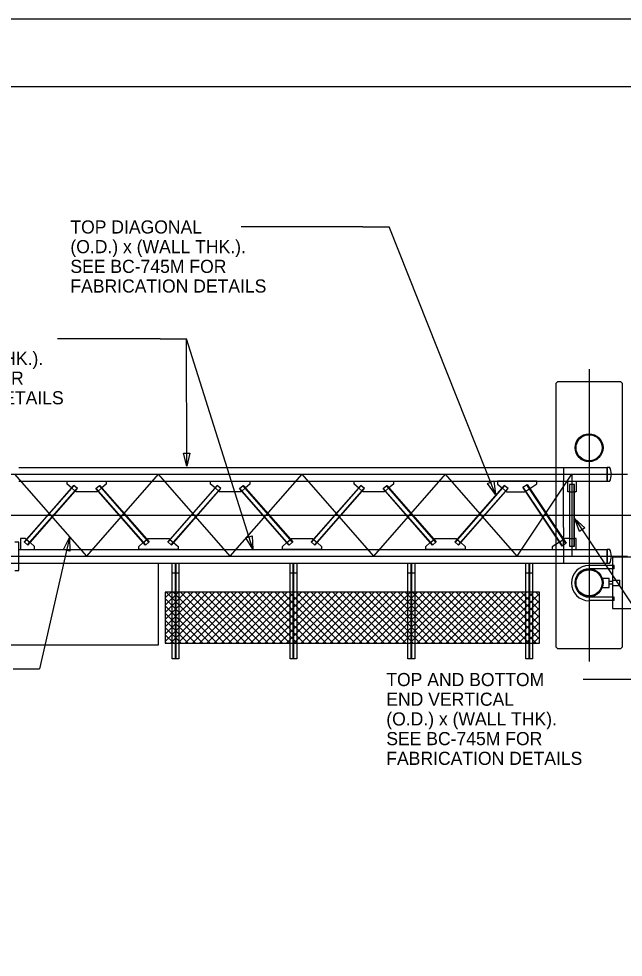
# Model space of a CAD drawing. Extents: x 3831399 to 3833095, y 499014 to 500202.
# Drawn here: x 3832620 to 3832754.1, y 499994 to 500202 of the extents above; entities that cross this region are included whole.
import ezdxf

# ---------------------------------------------------------------- set-up
doc = ezdxf.new("R2010")
doc.units = 0
for name, color, linetype in [('0-catwalk', 7, 'Continuous'), ('0-DEVICE ATTACH', 7, 'Continuous'), ('0-foundation', 7, 'Continuous'), ('0-sign', 7, 'Continuous'), ('0-truss', 7, 'Continuous'), ('2', 7, 'Continuous'), ('CenterLine', 7, 'Continuous'), ('DIM TXT', 7, 'Continuous'), ('PLT-BNDY', 7, 'Continuous'), ('structure', 7, 'Continuous')]:
    doc.layers.add(name, color=color, linetype=linetype)

msp = doc.modelspace()

# ---------------------------------------------------------------- linework, layer by layer
at = {"layer": '0-catwalk'}
for p, q in [((3832654.05, 500060.19), (3832654.05, 500081.38)), ((3832654.05, 500081.38), (3832655.54, 500081.38)), ((3832654.77, 500060.19), (3832654.77, 500081.38)), ((3832654.77, 500081.38), (3832654.83, 500081.38)), ((3832654.83, 500081.38), (3832654.83, 500060.19)), ((3832655.54, 500081.38), (3832655.54, 500060.19)), ((3832680.19, 500060.19), (3832680.19, 500081.38)), ((3832680.19, 500081.38), (3832681.69, 500081.38)), ((3832680.91, 500060.19), (3832680.91, 500081.38)), ((3832680.91, 500081.38), (3832680.97, 500081.38)), ((3832680.97, 500081.38), (3832680.97, 500060.19)), ((3832681.69, 500081.38), (3832681.69, 500060.19)), ((3832706.34, 500060.19), (3832706.34, 500081.38)), ((3832706.34, 500081.38), (3832707.83, 500081.38)), ((3832707.05, 500060.19), (3832707.05, 500081.38)), ((3832707.05, 500081.38), (3832707.12, 500081.38)), ((3832707.12, 500081.38), (3832707.12, 500060.19)), ((3832707.83, 500081.38), (3832707.83, 500060.19)), ((3832732.48, 500060.19), (3832732.48, 500081.38)), ((3832732.48, 500081.38), (3832733.98, 500081.38)), ((3832733.2, 500060.19), (3832733.2, 500081.38)), ((3832733.2, 500081.38), (3832733.26, 500081.38)), ((3832733.26, 500081.38), (3832733.26, 500060.19)), ((3832733.98, 500081.38), (3832733.98, 500060.19)), ((3832735.5, 500074.96), (3832652.52, 500074.96)), ((3832652.52, 500074.96), (3832652.52, 500063.6)), ((3832652.52, 500064.02), (3832663.47, 500074.96)), ((3832652.52, 500065.63), (3832661.86, 500074.96)), ((3832652.52, 500067.23), (3832660.25, 500074.96)), ((3832652.52, 500068.84), (3832658.65, 500074.96)), ((3832652.52, 500070.45), (3832657.04, 500074.96)), ((3832652.52, 500072.06), (3832655.43, 500074.96)), ((3832652.52, 500073.66), (3832653.82, 500074.96)), ((3832652.52, 500073.52), (3832662.45, 500063.6)), ((3832652.69, 500074.96), (3832664.06, 500063.6)), ((3832653.71, 500063.6), (3832665.08, 500074.96)), ((3832654.3, 500074.96), (3832665.67, 500063.6)), ((3832655.32, 500063.6), (3832666.68, 500074.96)), ((3832655.91, 500074.96), (3832667.27, 500063.6)), ((3832656.92, 500063.6), (3832668.29, 500074.96)), ((3832657.51, 500074.96), (3832668.88, 500063.6)), ((3832658.53, 500063.6), (3832669.9, 500074.96)), ((3832659.12, 500074.96), (3832670.49, 500063.6)), ((3832660.14, 500063.6), (3832671.51, 500074.96)), ((3832660.73, 500074.96), (3832672.1, 500063.6)), ((3832661.75, 500063.6), (3832673.11, 500074.96)), ((3832662.34, 500074.96), (3832673.7, 500063.6)), ((3832663.35, 500063.6), (3832674.72, 500074.96)), ((3832663.94, 500074.96), (3832675.31, 500063.6)), ((3832664.96, 500063.6), (3832676.33, 500074.96)), ((3832665.55, 500074.96), (3832676.92, 500063.6)), ((3832666.57, 500063.6), (3832677.94, 500074.96)), ((3832667.16, 500074.96), (3832678.53, 500063.6)), ((3832668.18, 500063.6), (3832679.54, 500074.96)), ((3832668.77, 500074.96), (3832680.13, 500063.6)), ((3832669.78, 500063.6), (3832681.15, 500074.96)), ((3832670.37, 500074.96), (3832681.74, 500063.6)), ((3832671.39, 500063.6), (3832682.76, 500074.96)), ((3832671.98, 500074.96), (3832683.35, 500063.6)), ((3832673, 500063.6), (3832684.37, 500074.96)), ((3832673.59, 500074.96), (3832684.96, 500063.6)), ((3832674.61, 500063.6), (3832685.97, 500074.96)), ((3832675.2, 500074.96), (3832686.56, 500063.6)), ((3832676.21, 500063.6), (3832687.58, 500074.96)), ((3832676.8, 500074.96), (3832688.17, 500063.6)), ((3832677.82, 500063.6), (3832689.19, 500074.96)), ((3832678.41, 500074.96), (3832689.78, 500063.6)), ((3832679.43, 500063.6), (3832690.8, 500074.96)), ((3832680.02, 500074.96), (3832691.39, 500063.6)), ((3832681.04, 500063.6), (3832692.4, 500074.96)), ((3832681.63, 500074.96), (3832692.99, 500063.6)), ((3832682.64, 500063.6), (3832694.01, 500074.96)), ((3832683.23, 500074.96), (3832694.6, 500063.6)), ((3832684.25, 500063.6), (3832695.62, 500074.96)), ((3832684.84, 500074.96), (3832696.21, 500063.6)), ((3832685.86, 500063.6), (3832697.23, 500074.96)), ((3832686.45, 500074.96), (3832697.82, 500063.6)), ((3832687.47, 500063.6), (3832698.83, 500074.96)), ((3832688.06, 500074.96), (3832699.42, 500063.6)), ((3832689.07, 500063.6), (3832700.44, 500074.96)), ((3832689.66, 500074.96), (3832701.03, 500063.6)), ((3832690.68, 500063.6), (3832702.05, 500074.96)), ((3832691.27, 500074.96), (3832702.64, 500063.6)), ((3832692.29, 500063.6), (3832703.66, 500074.96)), ((3832692.88, 500074.96), (3832704.25, 500063.6)), ((3832693.9, 500063.6), (3832705.26, 500074.96)), ((3832694.49, 500074.96), (3832705.85, 500063.6)), ((3832695.5, 500063.6), (3832706.87, 500074.96)), ((3832696.09, 500074.96), (3832707.46, 500063.6)), ((3832697.11, 500063.6), (3832708.48, 500074.96)), ((3832697.7, 500074.96), (3832709.07, 500063.6)), ((3832698.72, 500063.6), (3832710.09, 500074.96)), ((3832699.31, 500074.96), (3832710.68, 500063.6)), ((3832700.33, 500063.6), (3832711.69, 500074.96)), ((3832700.92, 500074.96), (3832712.28, 500063.6)), ((3832701.93, 500063.6), (3832713.3, 500074.96)), ((3832702.53, 500074.96), (3832713.89, 500063.6)), ((3832703.54, 500063.6), (3832714.91, 500074.96)), ((3832704.13, 500074.96), (3832715.5, 500063.6)), ((3832705.15, 500063.6), (3832716.52, 500074.96)), ((3832705.74, 500074.96), (3832717.11, 500063.6)), ((3832706.76, 500063.6), (3832718.12, 500074.96)), ((3832707.35, 500074.96), (3832718.71, 500063.6)), ((3832708.36, 500063.6), (3832719.73, 500074.96)), ((3832708.96, 500074.96), (3832720.32, 500063.6)), ((3832709.97, 500063.6), (3832721.34, 500074.96)), ((3832710.56, 500074.96), (3832721.93, 500063.6)), ((3832711.58, 500063.6), (3832722.95, 500074.96)), ((3832712.17, 500074.96), (3832723.54, 500063.6)), ((3832713.19, 500063.6), (3832724.55, 500074.96)), ((3832713.78, 500074.96), (3832725.14, 500063.6)), ((3832714.79, 500063.6), (3832726.16, 500074.96)), ((3832715.39, 500074.96), (3832726.75, 500063.6)), ((3832716.4, 500063.6), (3832727.77, 500074.96)), ((3832716.99, 500074.96), (3832728.36, 500063.6)), ((3832718.01, 500063.6), (3832729.38, 500074.96)), ((3832718.6, 500074.96), (3832729.97, 500063.6)), ((3832719.62, 500063.6), (3832730.98, 500074.96)), ((3832720.21, 500074.96), (3832731.57, 500063.6)), ((3832721.22, 500063.6), (3832732.59, 500074.96)), ((3832721.82, 500074.96), (3832733.18, 500063.6)), ((3832722.83, 500063.6), (3832734.2, 500074.96)), ((3832723.42, 500074.96), (3832734.79, 500063.6)), ((3832724.44, 500063.6), (3832735.5, 500074.66)), ((3832725.03, 500074.96), (3832735.5, 500064.49)), ((3832726.64, 500074.96), (3832735.5, 500066.1)), ((3832728.25, 500074.96), (3832735.5, 500067.71)), ((3832729.85, 500074.96), (3832735.5, 500069.31)), ((3832731.46, 500074.96), (3832735.5, 500070.92)), ((3832733.07, 500074.96), (3832735.5, 500072.53)), ((3832734.68, 500074.96), (3832735.5, 500074.14)), ((3832735.5, 500063.6), (3832735.5, 500074.96)), ((3832652.52, 500071.92), (3832660.84, 500063.6)), ((3832726.05, 500063.6), (3832735.5, 500073.05)), ((3832727.66, 500063.6), (3832735.5, 500071.44)), ((3832652.52, 500070.31), (3832659.24, 500063.6)), ((3832729.26, 500063.6), (3832735.5, 500069.84)), ((3832652.52, 500068.7), (3832657.63, 500063.6)), ((3832730.87, 500063.6), (3832735.5, 500068.23)), ((3832652.52, 500067.09), (3832656.02, 500063.6)), ((3832652.52, 500065.49), (3832654.41, 500063.6)), ((3832732.48, 500063.6), (3832735.5, 500066.62)), ((3832652.52, 500063.88), (3832652.81, 500063.6)), ((3832652.52, 500063.6), (3832735.5, 500063.6)), ((3832734.09, 500063.6), (3832735.5, 500065.01)), ((3832655.54, 500060.19), (3832654.05, 500060.19)), ((3832654.83, 500060.19), (3832654.77, 500060.19)), ((3832681.69, 500060.19), (3832680.19, 500060.19)), ((3832680.97, 500060.19), (3832680.91, 500060.19)), ((3832707.83, 500060.19), (3832706.34, 500060.19)), ((3832707.12, 500060.19), (3832707.05, 500060.19)), ((3832733.98, 500060.19), (3832732.48, 500060.19)), ((3832733.26, 500060.19), (3832733.2, 500060.19))]:
    msp.add_line(p, q, dxfattribs=at)
for points in [[(3832654.63, 500081.28), (3832654.05, 500081.28), (3832654.05, 500081.37), (3832655.54, 500081.37), (3832655.54, 500081.28), (3832654.96, 500081.28)], [(3832654.77, 500079.34), (3832654.77, 500081.15)], [(3832654.83, 500081.15), (3832654.83, 500079.34)], [(3832680.78, 500081.28), (3832680.19, 500081.28), (3832680.19, 500081.37), (3832681.69, 500081.37), (3832681.69, 500081.28), (3832681.11, 500081.28)], [(3832680.91, 500079.34), (3832680.91, 500081.15)], [(3832680.97, 500081.15), (3832680.97, 500079.34)], [(3832706.92, 500081.28), (3832706.34, 500081.28), (3832706.34, 500081.37), (3832707.83, 500081.37), (3832707.83, 500081.28), (3832707.25, 500081.28)], [(3832707.05, 500079.34), (3832707.05, 500081.15)], [(3832707.12, 500081.15), (3832707.12, 500079.34)], [(3832733.07, 500081.28), (3832732.48, 500081.28), (3832732.48, 500081.37), (3832733.98, 500081.37), (3832733.98, 500081.28), (3832733.39, 500081.28)], [(3832733.2, 500079.34), (3832733.2, 500081.15)], [(3832733.26, 500081.15), (3832733.26, 500079.34)], [(3832655.54, 500079.13), (3832654.05, 500079.13), (3832654.05, 500079.21), (3832654.63, 500079.21)], [(3832654.96, 500079.21), (3832655.54, 500079.21), (3832655.54, 500079.13)], [(3832681.69, 500079.13), (3832680.19, 500079.13), (3832680.19, 500079.21), (3832680.78, 500079.21)], [(3832681.11, 500079.21), (3832681.69, 500079.21), (3832681.69, 500079.13)], [(3832707.83, 500079.13), (3832706.34, 500079.13), (3832706.34, 500079.21), (3832706.92, 500079.21)], [(3832707.25, 500079.21), (3832707.83, 500079.21), (3832707.83, 500079.13)], [(3832733.98, 500079.13), (3832732.48, 500079.13), (3832732.48, 500079.21), (3832733.07, 500079.21)], [(3832733.39, 500079.21), (3832733.98, 500079.21), (3832733.98, 500079.13)]]:
    msp.add_lwpolyline(points, dxfattribs=at)
for centre, start, end in [((3832654.63, 500081.15), 0, 90), ((3832654.96, 500081.15), 90, 180), ((3832680.78, 500081.15), 0, 90), ((3832681.11, 500081.15), 90, 180), ((3832706.92, 500081.15), 0, 90), ((3832707.25, 500081.15), 90, 180), ((3832733.07, 500081.15), 0, 90), ((3832733.39, 500081.15), 90, 180), ((3832654.63, 500079.34), 270, 0), ((3832654.96, 500079.34), 180, 270), ((3832680.78, 500079.34), 270, 0), ((3832681.11, 500079.34), 180, 270), ((3832706.92, 500079.34), 270, 0), ((3832707.25, 500079.34), 180, 270), ((3832733.07, 500079.34), 270, 0), ((3832733.39, 500079.34), 180, 270)]:
    msp.add_arc(centre, 0.132, start, end, dxfattribs=at)
at = {"layer": '0-DEVICE ATTACH'}
for p, q in [((3832757.96, 500082.68), (3832751.71, 500082.68)), ((3832751.71, 500082.68), (3832751.71, 500071.31)), ((3832751.78, 500077.58), (3832753.3, 500077.58)), ((3832751.78, 500076.44), (3832753.3, 500076.44)), ((3832751.71, 500071.31), (3832757.96, 500071.31))]:
    msp.add_line(p, q, dxfattribs=at)
at = {"layer": '0-foundation'}
for p, q in [((3832739.48, 500121.53), (3832739.1, 500121.15)), ((3832753.5, 500121.53), (3832739.48, 500121.53)), ((3832753.88, 500121.15), (3832753.5, 500121.53)), ((3832739.1, 500121.15), (3832739.1, 500062.8)), ((3832753.88, 500062.8), (3832753.88, 500121.15)), ((3832740.81, 500102.58), (3832740.81, 500099.55)), ((3832740.81, 500089.26), (3832740.81, 500099.55)), ((3832740.81, 500089.26), (3832740.81, 500087.3)), ((3832740.81, 500085.5), (3832740.81, 500087.3)), ((3832740.81, 500085.5), (3832740.81, 500081.37)), ((3832739.1, 500062.8), (3832739.48, 500062.42)), ((3832739.48, 500062.42), (3832753.5, 500062.42)), ((3832753.5, 500062.42), (3832753.88, 500062.8))]:
    msp.add_line(p, q, dxfattribs=at)
at = {"layer": '0-sign'}
for p, q in [((3832537.29, 500081.37), (3832650.95, 500081.37)), ((3832650.95, 500081.37), (3832650.95, 500063.18)), ((3832650.95, 500063.18), (3832537.29, 500063.18))]:
    msp.add_line(p, q, dxfattribs=at)
at = {"layer": '0-truss'}
for p, q in [((3832620.03, 500102.58), (3832750.49, 500102.58)), ((3832750.49, 500102.66), (3832751.05, 500102.66)), ((3832750.49, 500102.58), (3832750.49, 500099.55)), ((3832620.03, 500099.55), (3832750.49, 500099.55)), ((3832632.22, 500098.61), (3832621.24, 500086.06)), ((3832621.3, 500086.01), (3832632.28, 500098.56)), ((3832631.72, 500098.04), (3832630.74, 500098.9)), ((3832633.04, 500097.89), (3832632.22, 500098.61)), ((3832637.15, 500097.89), (3832637.97, 500098.61)), ((3832648.89, 500086.01), (3832637.91, 500098.56)), ((3832637.97, 500098.61), (3832648.95, 500086.06)), ((3832639.45, 500098.9), (3832638.47, 500098.04)), ((3832664.05, 500098.61), (3832653.07, 500086.06)), ((3832653.12, 500086.01), (3832664.1, 500098.56)), ((3832663.55, 500098.04), (3832662.56, 500098.9)), ((3832664.87, 500097.89), (3832664.05, 500098.61)), ((3832668.98, 500097.89), (3832669.8, 500098.61)), ((3832680.72, 500086.01), (3832669.74, 500098.56)), ((3832669.8, 500098.61), (3832680.78, 500086.06)), ((3832671.28, 500098.9), (3832670.29, 500098.04)), ((3832695.87, 500098.61), (3832684.89, 500086.06)), ((3832684.95, 500086.01), (3832695.93, 500098.56)), ((3832695.38, 500098.04), (3832694.39, 500098.9)), ((3832696.69, 500097.89), (3832695.87, 500098.61)), ((3832700.81, 500097.89), (3832701.63, 500098.61)), ((3832712.55, 500086.01), (3832701.57, 500098.56)), ((3832701.63, 500098.61), (3832712.61, 500086.06)), ((3832703.11, 500098.9), (3832702.12, 500098.04)), ((3832727.7, 500098.61), (3832716.72, 500086.06)), ((3832727.76, 500098.56), (3832716.78, 500086.01)), ((3832726.22, 500098.9), (3832727.2, 500098.04)), ((3832728.52, 500097.89), (3832727.7, 500098.61)), ((3832731.84, 500098.19), (3832732.75, 500098.8)), ((3832741.37, 500085.72), (3832732.68, 500098.75)), ((3832732.75, 500098.8), (3832741.44, 500085.76)), ((3832733.34, 500097.9), (3832734.93, 500098.96)), ((3832742.16, 500098.8), (3832742.16, 500085.15)), ((3832743.25, 500098.8), (3832742.16, 500098.8)), ((3832742.23, 500085.15), (3832742.23, 500098.8)), ((3832743.17, 500085.15), (3832743.17, 500098.8)), ((3832743.25, 500085.15), (3832743.25, 500098.8)), ((3832622, 500085.39), (3832632.98, 500097.94)), ((3832622.06, 500085.34), (3832633.04, 500097.89)), ((3832631.72, 500098.04), (3832632.54, 500097.32)), ((3832632.76, 500097.14), (3832632.54, 500097.32)), ((3832648.13, 500085.34), (3832637.15, 500097.89)), ((3832648.19, 500085.39), (3832637.21, 500097.94)), ((3832637.65, 500097.32), (3832637.43, 500097.14)), ((3832637.65, 500097.32), (3832638.47, 500098.04)), ((3832653.83, 500085.39), (3832664.81, 500097.94)), ((3832653.89, 500085.34), (3832664.87, 500097.89)), ((3832663.55, 500098.04), (3832664.37, 500097.32)), ((3832664.58, 500097.14), (3832664.37, 500097.32)), ((3832679.96, 500085.34), (3832668.98, 500097.89)), ((3832680.02, 500085.39), (3832669.04, 500097.94)), ((3832669.47, 500097.32), (3832669.26, 500097.14)), ((3832669.47, 500097.32), (3832670.29, 500098.04)), ((3832685.65, 500085.39), (3832696.63, 500097.94)), ((3832685.71, 500085.34), (3832696.69, 500097.89)), ((3832695.38, 500098.04), (3832696.2, 500097.32)), ((3832696.41, 500097.14), (3832696.2, 500097.32)), ((3832711.79, 500085.34), (3832700.81, 500097.89)), ((3832711.84, 500085.39), (3832700.86, 500097.94)), ((3832701.3, 500097.32), (3832701.09, 500097.14)), ((3832701.3, 500097.32), (3832702.12, 500098.04)), ((3832728.46, 500097.94), (3832717.48, 500085.39)), ((3832717.54, 500085.34), (3832728.52, 500097.89)), ((3832727.2, 500098.04), (3832728.02, 500097.32)), ((3832728.02, 500097.32), (3832728.24, 500097.14)), ((3832728.24, 500097.14), (3832732.2, 500097.14)), ((3832740.53, 500085.15), (3832731.84, 500098.19)), ((3832740.6, 500085.2), (3832731.9, 500098.23)), ((3832732.2, 500097.14), (3832732.44, 500097.3)), ((3832732.44, 500097.3), (3832733.34, 500097.9)), ((3832742.16, 500097.14), (3832743.25, 500097.14)), ((3832620.03, 500086.03), (3832619.18, 500086.03)), ((3832620.03, 500079.73), (3832620.03, 500086.03)), ((3832621.52, 500086.81), (3832620.41, 500086.81)), ((3832620.41, 500086.81), (3832620.41, 500086.81)), ((3832620.41, 500086.81), (3832620.41, 500084.4)), ((3832621.24, 500086.06), (3832622.06, 500085.34)), ((3832621.73, 500086.63), (3832621.52, 500086.81)), ((3832621.73, 500086.63), (3832622.55, 500085.91)), ((3832623.54, 500085.05), (3832622.55, 500085.91)), ((3832646.65, 500085.05), (3832647.64, 500085.91)), ((3832647.64, 500085.91), (3832648.46, 500086.63)), ((3832648.95, 500086.06), (3832648.13, 500085.34)), ((3832648.46, 500086.63), (3832648.67, 500086.81)), ((3832653.07, 500086.06), (3832653.89, 500085.34)), ((3832653.35, 500086.81), (3832653.56, 500086.63)), ((3832653.56, 500086.63), (3832654.38, 500085.91)), ((3832654.38, 500085.91), (3832655.37, 500085.05)), ((3832678.48, 500085.05), (3832679.46, 500085.91)), ((3832679.46, 500085.91), (3832680.28, 500086.63)), ((3832680.78, 500086.06), (3832679.96, 500085.34)), ((3832680.28, 500086.63), (3832680.5, 500086.81)), ((3832684.89, 500086.06), (3832685.71, 500085.34)), ((3832685.17, 500086.81), (3832685.39, 500086.63)), ((3832685.39, 500086.63), (3832686.21, 500085.91)), ((3832686.21, 500085.91), (3832687.19, 500085.05)), ((3832710.31, 500085.05), (3832711.29, 500085.91)), ((3832711.29, 500085.91), (3832712.11, 500086.63)), ((3832712.61, 500086.06), (3832711.79, 500085.34)), ((3832712.11, 500086.63), (3832712.32, 500086.81)), ((3832716.72, 500086.06), (3832717.54, 500085.34)), ((3832717, 500086.81), (3832717.22, 500086.63)), ((3832717.22, 500086.63), (3832718.04, 500085.91)), ((3832718.04, 500085.91), (3832719.02, 500085.05)), ((3832739.93, 500086.05), (3832738.32, 500084.97)), ((3832739.93, 500086.05), (3832740.84, 500086.65)), ((3832741.08, 500086.81), (3832740.84, 500086.65)), ((3832742.16, 500086.81), (3832743.25, 500086.81)), ((3832620.03, 500084.4), (3832750.49, 500084.4)), ((3832741.44, 500085.76), (3832740.53, 500085.15)), ((3832742.16, 500085.15), (3832743.25, 500085.15)), ((3832750.49, 500084.47), (3832751.05, 500084.47)), ((3832750.49, 500084.4), (3832750.49, 500081.37)), ((3832619.18, 500079.73), (3832620.03, 500079.73)), ((3832620.03, 500081.37), (3832750.49, 500081.37))]:
    msp.add_line(p, q, dxfattribs=at)
for points in [[(3832751.05, 500099.48), (3832750.49, 500099.48), (3832750.49, 500102.66)], [(3832630.74, 500098.9), (3832630.74, 500099.55), (3832639.45, 500099.55), (3832639.45, 500098.9)], [(3832662.56, 500098.9), (3832662.56, 500099.55), (3832671.28, 500099.55), (3832671.28, 500098.9)], [(3832694.39, 500098.9), (3832694.39, 500099.55), (3832703.11, 500099.55), (3832703.11, 500098.9)], [(3832734.93, 500098.96), (3832734.93, 500099.55), (3832726.22, 500099.55), (3832726.22, 500098.9)], [(3832742.16, 500097.14), (3832741.78, 500097.14), (3832741.78, 500099.55), (3832743.62, 500099.55)], [(3832743.62, 500099.55), (3832743.62, 500097.14), (3832743.25, 500097.14)], [(3832637.43, 500097.14), (3832632.76, 500097.14)], [(3832669.26, 500097.14), (3832664.58, 500097.14)], [(3832701.09, 500097.14), (3832696.41, 500097.14)], [(3832743.25, 500097.14), (3832743.46, 500097.14)], [(3832648.67, 500086.81), (3832653.35, 500086.81)], [(3832680.5, 500086.81), (3832685.17, 500086.81)], [(3832712.32, 500086.81), (3832717, 500086.81)], [(3832738.32, 500084.97), (3832738.32, 500084.4), (3832743.62, 500084.4), (3832743.62, 500086.81), (3832743.25, 500086.81)], [(3832742.16, 500086.81), (3832741.08, 500086.81)], [(3832620.41, 500084.4), (3832623.54, 500084.4), (3832623.54, 500085.05)], [(3832655.37, 500085.05), (3832655.37, 500084.4), (3832646.65, 500084.4), (3832646.65, 500085.05)], [(3832687.19, 500085.05), (3832687.19, 500084.4), (3832678.48, 500084.4), (3832678.48, 500085.05)], [(3832719.02, 500085.05), (3832719.02, 500084.4), (3832710.31, 500084.4), (3832710.31, 500085.05)], [(3832751.05, 500081.29), (3832750.49, 500081.29), (3832750.49, 500084.47)]]:
    msp.add_lwpolyline(points, dxfattribs=at)
for centre, radius in [((3832746.49, 500106.94), 3.1), ((3832746.49, 500106.94), 3.03), ((3832746.49, 500106.94), 2.89), ((3832746.49, 500077.01), 3.1), ((3832746.49, 500077.01), 3.03), ((3832746.49, 500077.01), 2.89)]:
    msp.add_circle(centre, radius, dxfattribs=at)
for centre in [(3832747.95, 500101.07), (3832747.95, 500082.88)]:
    msp.add_arc(centre, 3.49, 332.944, 27.056, dxfattribs=at)
at = {"layer": '2'}
msp.add_line((3832280.16, 500187.03), (3833066.16, 500187.03), dxfattribs=at)
at = {"layer": 'CenterLine'}
for p, q in [((3832746.49, 500124.37), (3832746.49, 500059.58)), ((3832324.19, 500101.07), (3832755.03, 500101.07)), ((3832635.1, 500082.88), (3832619.18, 500101.07)), ((3832635.1, 500082.88), (3832651.01, 500101.07)), ((3832666.92, 500082.88), (3832651.01, 500101.07)), ((3832666.92, 500082.88), (3832682.84, 500101.07)), ((3832698.75, 500082.88), (3832682.84, 500101.07)), ((3832698.75, 500082.88), (3832714.66, 500101.07)), ((3832730.58, 500082.88), (3832714.66, 500101.07)), ((3832730.58, 500082.88), (3832742.7, 500101.07)), ((3832742.7, 500101.07), (3832742.7, 500082.88)), ((3832324.19, 500091.98), (3832755.03, 500091.98)), ((3832706.69, 500091.98), (3832762.11, 500091.98)), ((3832324.19, 500082.88), (3832755.03, 500082.88))]:
    msp.add_line(p, q, dxfattribs=at)
at = {"layer": 'DIM TXT'}
for p, q in [((3832696.36, 500155.89), (3832669.38, 500155.9)), ((3832696.36, 500155.89), (3832702.18, 500155.89)), ((3832725.74, 500096.61), (3832702.18, 500155.89)), ((3832651.42, 500131.12), (3832628.61, 500131.12)), ((3832651.42, 500131.12), (3832657.24, 500131.12)), ((3832651.42, 500131.12), (3832657.24, 500131.12)), ((3832671.96, 500084.43), (3832657.24, 500131.12)), ((3832657.27, 500102.83), (3832657.24, 500131.12)), ((3832743.36, 500091.18), (3832767, 500055.57)), ((3832631.31, 500087.04), (3832624.6, 500057.95)), ((3832618.78, 500057.95), (3832624.6, 500057.95)), ((3832761.18, 500055.57), (3832745.2, 500055.57))]:
    msp.add_line(p, q, dxfattribs=at)
for points in [[(3832658, 500105.74), (3832657.27, 500102.83), (3832656.54, 500105.74)], [(3832725.34, 500099.58), (3832725.74, 500096.61), (3832723.99, 500099.04)], [(3832744.36, 500088.36), (3832743.36, 500091.18), (3832745.57, 500089.16)], [(3832629.95, 500084.37), (3832631.31, 500087.04), (3832631.36, 500084.04)], [(3832671.78, 500087.42), (3832671.96, 500084.43), (3832670.39, 500086.98)]]:
    msp.add_lwpolyline(points, close=True, dxfattribs=at)
at = {"layer": 'PLT-BNDY'}
msp.add_lwpolyline([(3832240.16, 500202.03), (3833081.16, 500202.03), (3833081.16, 499608.03), (3832240.16, 499608.03)], close=True, dxfattribs=at)
at = {"layer": 'structure'}
for p, q in [((3832752.06, 500080.88), (3832746.49, 500080.88)), ((3832752.06, 500080.13), (3832746.49, 500080.13)), ((3832752.06, 500080.13), (3832752.06, 500080.88)), ((3832749.43, 500078.03), (3832750.97, 500078.03)), ((3832750.97, 500075.99), (3832750.97, 500078.03)), ((3832751.78, 500076.44), (3832751.78, 500077.58)), ((3832753.3, 500076.44), (3832753.3, 500077.58)), ((3832749.43, 500075.99), (3832750.97, 500075.99)), ((3832751.78, 500077.29), (3832750.97, 500077.29)), ((3832751.78, 500076.72), (3832750.97, 500076.72)), ((3832752.06, 500073.84), (3832746.49, 500073.84)), ((3832752.06, 500073.08), (3832752.06, 500073.84)), ((3832752.06, 500073.08), (3832746.49, 500073.08))]:
    msp.add_line(p, q, dxfattribs=at)
for centre, radius in [((3832746.49, 500076.96), 3.92), ((3832746.49, 500076.98), 3.13)]:
    msp.add_arc(centre, radius, 90, 270, dxfattribs=at)

# ---------------------------------------------------------------- texts
at = {"layer": 'DIM TXT'}
for s, p in [('TOP DIAGONAL', (3832631.48, 500154.43)), ('(O.D.) x (WALL THK.).', (3832631.48, 500150.07)), ('SEE BC-745M FOR', (3832631.48, 500145.7)), ('FABRICATION DETAILS', (3832631.48, 500141.34)), ('(O.D.) x (WALL THK.).', (3832586.54, 500125.3)), ('SEE BC-745M FOR', (3832586.54, 500120.93)), ('FABRICATION DETAILS', (3832586.54, 500116.57)), ('TOP AND BOTTOM', (3832701.53, 500054.11)), ('END VERTICAL', (3832701.53, 500049.75)), ('(O.D.) x (WALL THK).', (3832701.53, 500045.38)), ('SEE BC-745M FOR', (3832701.53, 500041.02)), ('FABRICATION DETAILS', (3832701.53, 500036.65))]:
    msp.add_text(s, height=2.9099, dxfattribs=at).set_placement(p)

doc.saveas('drawing.dxf')
